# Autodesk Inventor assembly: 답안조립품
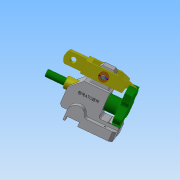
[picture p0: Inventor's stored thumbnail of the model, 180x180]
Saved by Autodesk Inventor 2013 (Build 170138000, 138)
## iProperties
Created: 2016-11
Part Number: 답안조립품
Document SubType Name: Assembly
Designer: Administrator
Author: Administrator
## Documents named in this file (8)
- C:\Users\Administrator\Desktop\461108V1026\답안조립품.iam
- C:\Users\Administrator\Desktop\461108V1026\본체.ipt
- C:\Users\Administrator\Desktop\461108V1026\부시.ipt
- C:\Users\Administrator\Desktop\461108V1026\분할대.ipt
- C:\Users\Administrator\Desktop\461108V1026\분할축.ipt
- C:\Users\Administrator\Desktop\461108V1026\와셔.ipt
- C:\Users\Administrator\Desktop\461108V1026\원통형핀.ipt
- C:\Users\Administrator\Desktop\461108V1026\클레비스핀.ipt
